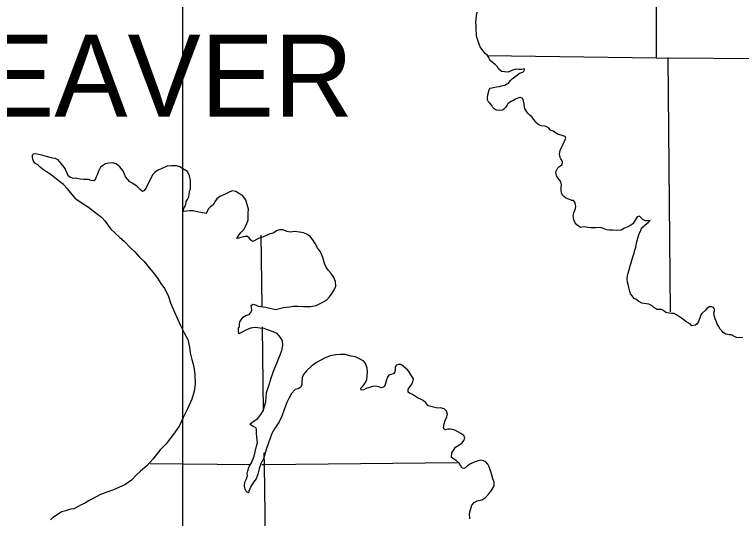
# Model space of a CAD drawing. Extents: x 77230 to 630905, y 790554 to 1662844.
# Drawn here: x 293730 to 303084, y 1579482 to 1585968 of the extents above; entities that cross this region are included whole.
import ezdxf

# ---------------------------------------------------------------- set-up
doc = ezdxf.new("R2010")
doc.units = 0
for name, color, linetype in [('Level 15', 7, 'Continuous'), ('Level 16', 7, 'Continuous'), ('Level 17', 7, 'Continuous'), ('Level 28', 7, 'Continuous')]:
    doc.layers.add(name, color=color, linetype=linetype)

msp = doc.modelspace()

# ---------------------------------------------------------------- linework, layer by layer
at = {"layer": 'Level 15'}
msp.add_lwpolyline([(299812.2, 1585441.6), (301992.1, 1585408.8), (304916.6, 1585392.6)], dxfattribs=at)
at = {"layer": 'Level 16'}
for points in [[(301990, 1585412.8), (301999, 1588104.1)], [(302171.2, 1582141.9), (302141.6, 1585413.9)], [(296900.5, 1583127.3), (296912.9, 1582215.2)], [(296916.5, 1581947.6), (296931.1, 1580864.3)], [(296938.4, 1580328.6), (296940.6, 1580164.7), (297010.1, 1575166.3)], [(296764.4, 1580173.9), (295474.3, 1580183.5)], [(299429, 1580200.2), (296932.6, 1580172.6), (296910, 1580172.8)]]:
    msp.add_lwpolyline(points, dxfattribs=at)
at = {"layer": 'Level 17'}
for points in [[(300716, 1584429.8), (300661.9, 1584465.3), (300625.8, 1584479.1), (300599.6, 1584510.9), (300571.6, 1584526.7), (300549.6, 1584530.5), (300507.7, 1584534.2), (300477.6, 1584547.9), (300447.5, 1584569.7), (300437.4, 1584587.6), (300409.2, 1584623.4), (300389, 1584645.3), (300358.9, 1584671), (300338.8, 1584694.9), (300320.6, 1584716.8), (300298.3, 1584760.6), (300294.2, 1584780.6), (300289.9, 1584810.6), (300287.9, 1584820.6), (300275.5, 1584874.5), (300263.4, 1584890.4), (300239.3, 1584902.2), (300231.4, 1584900.2), (300207.5, 1584890), (300185.6, 1584881.8), (300151.8, 1584861.5), (300122, 1584849.3), (300088.3, 1584829), (300072.4, 1584814.9), (300068.5, 1584800.8), (300050.8, 1584776.7), (300023.1, 1584746.4), (300007.2, 1584736.3), (299971.3, 1584734), (299927.4, 1584737.7), (299901.3, 1584753.5), (299883.2, 1584773.3), (299871, 1584799.2), (299852.9, 1584817.1), (299834.8, 1584835), (299814.6, 1584870.8), (299816.3, 1584898.9), (299822, 1584932.9), (299835.5, 1585001.1), (299851.3, 1585021.2), (299895.1, 1585029.6), (299931, 1585035.8), (299968.8, 1585042.1), (299996.7, 1585050.4), (300038.5, 1585058.7), (300062.4, 1585070.9), (300086.2, 1585085.1), (300096.1, 1585097.2), (300113.9, 1585119.3), (300135.6, 1585143.5), (300145.5, 1585149.6), (300173.3, 1585171.8), (300201.1, 1585194.1), (300236.8, 1585216.4), (300270.6, 1585228.6), (300286.5, 1585244.8), (300290.3, 1585268.8), (300254.4, 1585262.5), (300218.5, 1585262.2), (300184.5, 1585264), (300138.7, 1585253.6), (300110.9, 1585237.4), (300077.1, 1585225.1), (300033.1, 1585232.8), (299995.2, 1585236.5), (299963, 1585264.2), (299944.8, 1585294.1), (299918.7, 1585321.9), (299880.5, 1585349.6), (299846.4, 1585381.4), (299834.1, 1585413.3), (299814, 1585439.1), (299787.8, 1585464.9), (299755.6, 1585506.7), (299721.3, 1585552.5), (299707, 1585588.4), (299694.8, 1585626.3), (299676.3, 1585688.2), (299676.1, 1585716.2), (299671.6, 1585776.2), (299669.3, 1585820.2), (299664.8, 1585872.2), (299668.6, 1585904.2), (299676.1, 1585956.3), (299683.8, 1586000.4)], [(301713.7, 1582936.9), (301725.4, 1582975), (301729.1, 1583003), (301738.8, 1583041.1), (301750.4, 1583091.2), (301760.1, 1583121.3), (301773.8, 1583157.5), (301787.5, 1583189.6), (301799.3, 1583217.7), (301830.9, 1583250), (301840.8, 1583258.1), (301864.6, 1583278.3), (301884.5, 1583292.4), (301908.2, 1583316.6), (301882.3, 1583314.4), (301854.4, 1583314.2), (301818.4, 1583323.9), (301796.2, 1583345.7), (301770.1, 1583371.6), (301740.2, 1583365.3), (301716.6, 1583323.1), (301685.1, 1583274.8), (301661.3, 1583256.6), (301621.5, 1583234.3), (301579.8, 1583218), (301534.1, 1583193.6), (301476.3, 1583187.1), (301430.3, 1583190.8), (301386.4, 1583194.4), (301350.5, 1583198.1), (301308.4, 1583215.8), (301264.4, 1583225.5), (301204.6, 1583223), (301150.7, 1583224.6), (301106.8, 1583226.2), (301058.8, 1583233.8), (301013, 1583227.5), (300964.8, 1583261.1), (300942.7, 1583288.9), (300926.4, 1583326.8), (300922.2, 1583354.8), (300920, 1583382.8), (300927.7, 1583416.9), (300949.2, 1583471.1), (300953, 1583497.1), (300948.8, 1583525.1), (300940.5, 1583555.1), (300922.4, 1583574.9), (300900.5, 1583574.8), (300850.4, 1583594.4), (300820.4, 1583608.1), (300798.3, 1583628), (300782.2, 1583643.9), (300768, 1583673.8), (300763.7, 1583711.7), (300765.4, 1583749.8), (300769.2, 1583775.8), (300760.9, 1583813.8), (300736.7, 1583845.6), (300712.5, 1583875.4), (300700.3, 1583907.3), (300696, 1583945.3), (300703.8, 1583961.4), (300719.5, 1583993.5), (300735.3, 1584009.7), (300771.1, 1584034), (300780.9, 1584058.1), (300780.7, 1584078.1), (300758.5, 1584109.9), (300752.4, 1584127.9), (300742, 1584169.8), (300751.6, 1584217.9), (300767.3, 1584256.1), (300788.9, 1584298.3), (300820.3, 1584366.5), (300822.2, 1584376.6), (300814, 1584400.5), (300762, 1584414.1), (300716, 1584429.8)], [(294518.9, 1583595.3), (294407.3, 1583730.1), (294361.2, 1583780), (294309.2, 1583819.8), (294269.1, 1583849.7), (294223, 1583887.5), (294183, 1583917.3), (294139, 1583943.2), (294090.9, 1583979), (294054.9, 1584008.9), (294028.8, 1584034.8), (293992.8, 1584056.7), (293972.7, 1584080.6), (293964.7, 1584106.6), (293958.6, 1584132.6), (293960.5, 1584160.6), (293974.5, 1584176.6), (294002.4, 1584180.7), (294038.4, 1584170.9), (294076.4, 1584163), (294136.4, 1584147.3), (294182.4, 1584131.4), (294218.3, 1584123.6), (294250.3, 1584121.7), (294282.3, 1584101.8), (294326.4, 1584052), (294364.5, 1584004.1), (294380.6, 1583978.1), (294396.7, 1583940.2), (294416.8, 1583902.3), (294440.8, 1583880.3), (294472.8, 1583868.5), (294510.9, 1583864.2)], [(295535.9, 1583936.4), (295504.3, 1583904.1), (295472.9, 1583841.8), (295449.3, 1583795.6), (295431.7, 1583753.5), (295412, 1583721.3), (295394.2, 1583697.1), (295374.3, 1583691), (295346.1, 1583716.8), (295305.9, 1583754.5), (295251.7, 1583794.1), (295213.7, 1583815.8), (295185.5, 1583845.6), (295159.3, 1583877.4), (295143, 1583913.3), (295122.7, 1583959.1), (295086.4, 1584006.9), (295036.2, 1584048.5), (294992.2, 1584060.1), (294944.4, 1584055.8), (294900.5, 1584047.4), (294835, 1584002.9), (294811.5, 1583950.6), (294795.8, 1583914.5), (294780.2, 1583878.4), (294766.5, 1583842.2), (294750.6, 1583826.1), (294714.7, 1583831.8), (294680.7, 1583843.5), (294616.8, 1583845), (294572.9, 1583848.7), (294510.9, 1583864.2)], [(296964.6, 1582202.8), (297086.5, 1582173.7), (297192.1, 1582198.6), (297269.9, 1582205.2), (297317.7, 1582215.6), (297373.5, 1582214), (297449.4, 1582208.6), (297537.2, 1582211.3), (297610.9, 1582221.9), (297690.4, 1582260.6), (297742.1, 1582293), (297781.6, 1582335.3), (297817.2, 1582383.7), (297842.8, 1582425.9), (297862.4, 1582470.1), (297857.9, 1582530.1), (297837.5, 1582581.9), (297803.2, 1582635.7), (297768.9, 1582673.4), (297738.7, 1582717.2), (297716.3, 1582765.1), (297695.8, 1582840.9), (297665.2, 1582914.7), (297628.9, 1582966.5), (297598.5, 1583020.3), (297570.2, 1583068.1), (297536, 1583111.8), (297489.8, 1583141.5), (297449.8, 1583159.2), (297397.8, 1583168.7), (297333.9, 1583174.2), (297282.1, 1583167.8), (297232.1, 1583177.4), (297188.1, 1583197.1), (297138.2, 1583198.7), (297102.4, 1583182.4), (297066.7, 1583160.1), (297038.8, 1583151.9), (297020.9, 1583145.7), (296959.2, 1583121.2), (296919.4, 1583104.9), (296875.7, 1583088.6), (296849.8, 1583076.3), (296814.1, 1583054.1), (296792.2, 1583047.9), (296768.1, 1583067.7), (296749.9, 1583093.6), (296725.8, 1583111.4), (296695.9, 1583111.1), (296642.1, 1583098.7), (296610.3, 1583088.5), (296588.3, 1583086.3), (296610, 1583120.5), (296641.6, 1583162.7), (296679.2, 1583203.1), (296712.6, 1583267.4), (296734.1, 1583325.6), (296735.4, 1583411.6), (296741, 1583463.7), (296720.4, 1583537.6), (296708.1, 1583583.5), (296663.7, 1583637.2), (296623.6, 1583660.9), (296579.5, 1583692.5), (296529.5, 1583700.1), (296481.8, 1583677.8), (296432.2, 1583653.3), (296370.5, 1583624.8), (296334.8, 1583594.5), (296305.2, 1583556.3), (296285.6, 1583520.1), (296251.9, 1583491.8), (296224.1, 1583467.6), (296208.4, 1583435.5), (296194.7, 1583405.3), (296128.7, 1583418.8), (296078.8, 1583430.4), (296028.8, 1583442), (295978.9, 1583439.6), (295941, 1583435.3), (295909.1, 1583433.1), (295902.9, 1583469), (295924.5, 1583501.2), (295932.3, 1583529.3), (295940, 1583563.4), (295955.8, 1583585.5), (295971.5, 1583623.7), (295980.9, 1583689.8), (295992.6, 1583725.9), (295996.1, 1583788), (295995.7, 1583832), (295979.3, 1583893.9), (295954.9, 1583947.7), (295904.7, 1583979.3), (295856.6, 1584007), (295812.6, 1584020.6), (295750.8, 1584020.1), (295694.9, 1584015.7), (295623.3, 1583987.1), (295567.7, 1583962.6), (295535.9, 1583936.4)], [(294518.9, 1583595.3), (294611.2, 1583532.1), (294683.4, 1583488.8), (294798, 1583399.8), (294848.2, 1583358.3), (294894.5, 1583310.7), (294934.9, 1583255), (294969.3, 1583207.3), (295021.6, 1583157.8), (295086, 1583096.4), (295140.3, 1583052.9), (295220.9, 1582967.6), (295279.2, 1582912.1), (295335.7, 1582846.6), (295398, 1582789.2), (295460.6, 1582707.7), (295515.1, 1582646.2), (295567.6, 1582574.7), (295614.1, 1582505.1), (295660.6, 1582441.5), (295705.2, 1582353.9), (295736, 1582258.1), (295789, 1582138.6), (295827.7, 1582052.9), (295866.4, 1581967.2), (295915.2, 1581863.7), (295959.8, 1581786), (295982.6, 1581686.2), (295991.3, 1581614.3), (296010, 1581530.4), (296038.8, 1581432.6), (296049.7, 1581336.7), (296052.8, 1581210.7), (296039.7, 1581120.5), (296012.7, 1581016.2), (295956, 1580891.6), (295901.1, 1580783.1), (295846.3, 1580668.5), (295775.4, 1580565.8), (295682.7, 1580444.8), (295605.6, 1580364.1), (295512.9, 1580251.2), (295432, 1580158.4), (295350.8, 1580089.6), (295299.3, 1580045.1), (295234.1, 1579974.4), (295146.9, 1579915.6), (295003.8, 1579852.2), (294928.3, 1579823.5), (294828.8, 1579786.5), (294741.5, 1579737.7), (294679.9, 1579709.1), (294638.3, 1579680.7), (294568.7, 1579650)], [(303103.6, 1581811.3), (303049.7, 1581806.9), (303019.7, 1581812.6), (302995.7, 1581824.4), (302957.6, 1581844.2), (302927.7, 1581847.9), (302883.7, 1581853.6), (302847.6, 1581875.3), (302831.5, 1581897.2), (302805.3, 1581923), (302791.2, 1581950.9), (302772.9, 1581982.8), (302762.7, 1582012.7), (302746.5, 1582050.6), (302738.2, 1582080.5), (302729.9, 1582122.5), (302735.7, 1582152.6), (302737.5, 1582170.6), (302727.4, 1582192.5), (302703.3, 1582204.3), (302667.4, 1582208), (302633.7, 1582179.8), (302615.9, 1582159.6), (302578.2, 1582125.3), (302560.4, 1582105.1), (302550.7, 1582073.1), (302539, 1582042.9), (302533.2, 1582018.9), (302509.5, 1581984.7), (302491.7, 1581970.5), (302445.9, 1581960.2), (302425.7, 1581986), (302373.6, 1582011.6), (302327.4, 1582051.3), (302285.3, 1582076.9), (302249.2, 1582102.7), (302219.1, 1582118.4), (302183.2, 1582122.2), (302153.2, 1582123.9), (302111.3, 1582133.6), (302081.1, 1582157.4), (302055.1, 1582171.2), (302019.2, 1582170.9), (301993.2, 1582170.7), (301957.1, 1582196.4), (301935, 1582218.2), (301890.9, 1582241.9), (301803, 1582251.2), (301762.9, 1582276.9), (301728.8, 1582298.6), (301704.8, 1582312.5), (301676.6, 1582346.3), (301654.4, 1582372.1), (301646.2, 1582402), (301633.8, 1582454), (301625.5, 1582491.9), (301619.3, 1582523.9), (301614.9, 1582567.9), (301616.6, 1582605.9), (301626.3, 1582640), (301647.7, 1582712.2), (301653.5, 1582732.3), (301665.2, 1582770.4), (301678.7, 1582820.5), (301692.4, 1582860.7), (301702.1, 1582894.8), (301713.7, 1582936.9)], [(297184, 1581714.3), (297177.6, 1581770.3), (297153.3, 1581812.1), (297111, 1581863.8), (297056.9, 1581883.4), (296984.9, 1581908.8), (296940.9, 1581926.5), (296886.9, 1581932), (296827, 1581939.6), (296765.2, 1581931.1), (296697.6, 1581902.5), (296657.9, 1581880.2), (296618.1, 1581859.9), (296611.9, 1581897.8), (296611.6, 1581931.8), (296625.4, 1581950), (296625.1, 1581982), (296628.9, 1582012), (296654.5, 1582050.3), (296672.3, 1582072.4), (296702.1, 1582094.7), (296747.9, 1582107), (296769.6, 1582133.2), (296783.3, 1582165.3), (296779.1, 1582197.3), (296774.9, 1582223.3), (296794.7, 1582241.5), (296828.7, 1582231.7), (296866.7, 1582216), (296964.6, 1582202.8)], [(298573.8, 1581335.1), (298548, 1581324.9), (298530.2, 1581300.7), (298514.5, 1581266.6), (298508.8, 1581238.5), (298497.1, 1581204.4), (298489.3, 1581180.3), (298477.4, 1581170.2), (298449.5, 1581164), (298429.5, 1581171.9), (298397.5, 1581181.6), (298369.5, 1581183.4), (298337.6, 1581181.1), (298295.8, 1581168.8), (298256, 1581154.5), (298226.2, 1581138.2), (298190.4, 1581131.9), (298186.2, 1581157.9), (298215.8, 1581190.2), (298241.5, 1581226.4), (298263.1, 1581266.6), (298268.7, 1581320.7), (298272.3, 1581362.7), (298265.9, 1581416.7), (298249.5, 1581466.6), (298225.3, 1581506.4), (298169.2, 1581536), (298117.1, 1581563.6), (298063.1, 1581573.2), (297983.2, 1581590.5), (297925.3, 1581592.1), (297863.4, 1581589.6), (297791.7, 1581575), (297718.1, 1581546.4), (297670.5, 1581518), (297616.8, 1581489.6), (297557.3, 1581445.1), (297488, 1581384.5), (297448.4, 1581336.2), (297430.8, 1581298), (297427.3, 1581235.9), (297427.6, 1581201.9), (297413.8, 1581173.8), (297378.1, 1581151.5), (297342.2, 1581141.2), (297292.8, 1581088.8), (297257.4, 1581026.5), (297231.8, 1580976.3), (297200.6, 1580886), (297167.4, 1580799.7), (297136.1, 1580725.4), (297076.9, 1580636.8), (297039.5, 1580574.5), (296996.6, 1580456.1), (296967.3, 1580371.8), (296932.3, 1580251.5), (296898.9, 1580189.2), (296875.5, 1580121), (296862.1, 1580052.8), (296840.6, 1579992.6), (296803.1, 1579948.3), (296769.6, 1579894), (296755.9, 1579863.9), (296746.1, 1579833.8), (296742.3, 1579813.8), (296716.3, 1579823.6), (296696.1, 1579857.4), (296689.7, 1579899.4), (296695.3, 1579949.5), (296714.9, 1579991.6), (296726.6, 1580035.7), (296724.4, 1580061.7), (296730.1, 1580095.8), (296749.6, 1580150), (296777.1, 1580198.2), (296794.8, 1580240.4), (296814.4, 1580282.6), (296827.9, 1580340.7), (296841.3, 1580410.9), (296856.8, 1580461), (296846.3, 1580525), (296841.9, 1580583), (296841.6, 1580621), (296839.4, 1580649), (296801.3, 1580664.7), (296775.2, 1580684.5), (296759.2, 1580694.4), (296798.8, 1580730.7), (296862.4, 1580767.2), (296899.9, 1580819.5), (296929.4, 1580867.8), (296944.9, 1580928), (296962.4, 1580982.1), (296971.4, 1581104.3), (297000.7, 1581188.5), (297033.8, 1581290.9), (297070.8, 1581401.2), (297104.1, 1581481.5), (297137.3, 1581565.8), (297170.6, 1581642.1), (297184, 1581714.3)], [(299586.5, 1579476.1), (299585.9, 1579548.2), (299595.5, 1579594.3), (299615, 1579654.5), (299642.6, 1579686.7), (299684.4, 1579709), (299742.1, 1579721.5), (299785.8, 1579749.9), (299833.3, 1579798.3), (299872.8, 1579850.6), (299900.3, 1579900.9), (299901.9, 1579950.9), (299885.6, 1579990.8), (299871.3, 1580040.7), (299856.9, 1580084.6), (299838.5, 1580148.5), (299822.2, 1580182.4), (299794.1, 1580210.2), (299766, 1580222), (299724.1, 1580231.6), (299694.2, 1580225.4), (299644.4, 1580209), (299598.7, 1580186.6), (299559, 1580160.3), (299537.2, 1580140.1), (299509.4, 1580125.9), (299489.4, 1580131.7), (299471.2, 1580161.6), (299451, 1580195.4), (299412.8, 1580227.2), (299390.7, 1580243), (299366.7, 1580258.8), (299352.6, 1580266.7), (299358.1, 1580326.8), (299381.8, 1580365), (299405.5, 1580399.2), (299449.1, 1580425.6), (299490.8, 1580455.9), (299512.5, 1580486.1), (299522.2, 1580516.2), (299510, 1580548.1), (299473.9, 1580575.8), (299433.8, 1580595.5), (299397.7, 1580617.3), (299365.7, 1580629), (299337.7, 1580632.8), (299303.8, 1580630.5), (299276, 1580622.3), (299257.9, 1580630.1), (299247.8, 1580654.1), (299259.4, 1580700.2), (299271, 1580742.3), (299294.6, 1580790.5), (299302.3, 1580826.6), (299288, 1580864.5), (299259.8, 1580894.3), (299211.8, 1580907.9), (299171.9, 1580901.6), (299140, 1580909.4), (299102, 1580919.1), (299074, 1580926.8), (299046, 1580934.6), (299021.7, 1580972.5), (298989.6, 1581000.2), (298955.5, 1581018), (298915.5, 1581033.6), (298887.4, 1581053.4), (298851.3, 1581079.2), (298811.2, 1581092.9), (298795.2, 1581108.7), (298796.8, 1581146.8), (298820.5, 1581181), (298840.2, 1581211.1), (298854, 1581241.3), (298861.6, 1581279.4), (298839.4, 1581317.2), (298813.1, 1581361), (298788.9, 1581390.8), (298762.8, 1581416.6), (298730.6, 1581444.4), (298702.5, 1581462.2), (298670.6, 1581465.9), (298642.7, 1581455.7), (298627, 1581423.6), (298627.3, 1581389.6), (298625.4, 1581369.5), (298607.7, 1581345.4), (298573.8, 1581335.1)], [(294194.2, 1579465.6), (294228.1, 1579499.7), (294270, 1579527.9), (294315.8, 1579558.1), (294339.8, 1579570.2), (294389.7, 1579586.4), (294453.5, 1579604.6), (294497.5, 1579610.8)], [(294497.5, 1579610.8), (294568.7, 1579650)]]:
    msp.add_lwpolyline(points, dxfattribs=at)
at = {"layer": 'Level 28'}
msp.add_line((295896.4, 1483323.9), (295896.4, 1662843.6), dxfattribs=at)

# ---------------------------------------------------------------- texts
at = {"layer": 'Level 17'}
msp.add_text('BEAVER', height=1056, dxfattribs=at).set_placement((292358.1, 1584652.4))

doc.saveas('drawing.dxf')
